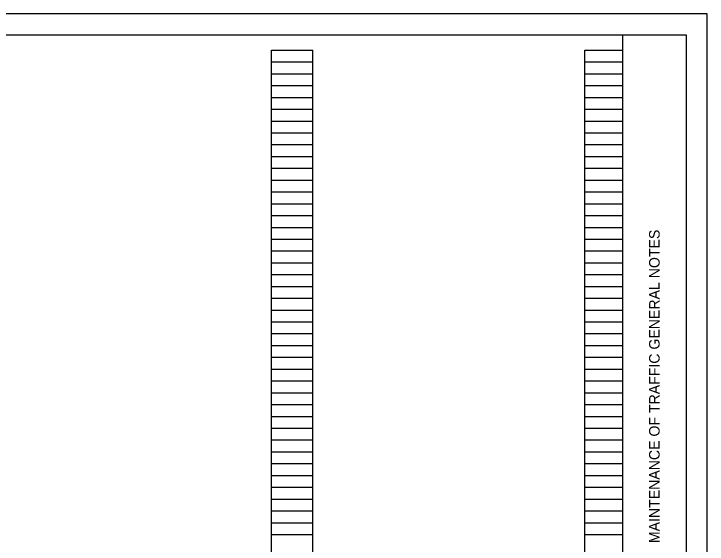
# Model space of a CAD drawing. Extents: x 0 to 34, y 0 to 22.
# Drawn here: x 17.58 to 34, y 9.43 to 22 of the extents above; entities that cross this region are included whole.
import ezdxf

# ---------------------------------------------------------------- set-up
doc = ezdxf.new("R2010")
doc.units = 0
for name, color, linetype in [('SH_Border', 7, 'Continuous'), ('SH_Cut_Line', 7, 'Continuous'), ('SH_Data', 7, 'Continuous')]:
    doc.layers.add(name, color=color, linetype=linetype)

msp = doc.modelspace()

# ---------------------------------------------------------------- linework, layer by layer
at = {"layer": 'SH_Border'}
msp.add_line((32, 0.5), (32, 21.5), dxfattribs=at)
msp.add_lwpolyline([(1.5, 21.5), (33.5, 21.5), (33.5, 0.5), (1.5, 0.5)], close=True, dxfattribs=at)
at = {"layer": 'SH_Cut_Line'}
msp.add_lwpolyline([(0, 0), (34, 0), (34, 22), (0, 22)], close=True, dxfattribs=at)
at = {"layer": 'SH_Data'}
for p, q in [((23.68, 0.98), (23.68, 21.14)), ((23.68, 21.14), (24.66, 21.14)), ((24.66, 0.98), (24.66, 21.14)), ((31.1, 0.98), (31.1, 21.14)), ((31.1, 21.14), (32, 21.14)), ((32, 0.98), (32, 21.14)), ((23.68, 20.86), (24.66, 20.86)), ((31.1, 20.86), (32, 20.86)), ((23.68, 20.58), (24.66, 20.58)), ((31.1, 20.58), (32, 20.58)), ((23.68, 20.3), (24.66, 20.3)), ((31.1, 20.3), (32, 20.3)), ((23.68, 20.02), (24.66, 20.02)), ((31.1, 20.02), (32, 20.02)), ((23.68, 19.74), (24.66, 19.74)), ((31.1, 19.74), (32, 19.74)), ((23.68, 19.46), (24.66, 19.46)), ((31.1, 19.46), (32, 19.46)), ((23.68, 19.18), (24.66, 19.18)), ((31.1, 19.18), (32, 19.18)), ((23.68, 18.9), (24.66, 18.9)), ((31.1, 18.9), (32, 18.9)), ((23.68, 18.62), (24.66, 18.62)), ((31.1, 18.62), (32, 18.62)), ((23.68, 18.34), (24.66, 18.34)), ((31.1, 18.34), (32, 18.34)), ((23.68, 18.06), (24.66, 18.06)), ((31.1, 18.06), (32, 18.06)), ((23.68, 17.78), (24.66, 17.78)), ((31.1, 17.78), (32, 17.78)), ((23.68, 17.5), (24.66, 17.5)), ((31.1, 17.5), (32, 17.5)), ((23.68, 17.22), (24.66, 17.22)), ((31.1, 17.22), (32, 17.22)), ((23.68, 16.94), (24.66, 16.94)), ((31.1, 16.94), (32, 16.94)), ((23.68, 16.66), (24.66, 16.66)), ((31.1, 16.66), (32, 16.66)), ((23.68, 16.38), (24.66, 16.38)), ((31.1, 16.38), (32, 16.38)), ((23.68, 16.1), (24.66, 16.1)), ((31.1, 16.1), (32, 16.1)), ((23.68, 15.82), (24.66, 15.82)), ((31.1, 15.82), (32, 15.82)), ((23.68, 15.54), (24.66, 15.54)), ((31.1, 15.54), (32, 15.54)), ((23.68, 15.26), (24.66, 15.26)), ((31.1, 15.26), (32, 15.26)), ((23.68, 14.98), (24.66, 14.98)), ((31.1, 14.98), (32, 14.98)), ((23.68, 14.7), (24.66, 14.7)), ((31.1, 14.7), (32, 14.7)), ((23.68, 14.42), (24.66, 14.42)), ((31.1, 14.42), (32, 14.42)), ((23.68, 14.14), (24.66, 14.14)), ((31.1, 14.14), (32, 14.14)), ((23.68, 13.86), (24.66, 13.86)), ((31.1, 13.86), (32, 13.86)), ((23.68, 13.58), (24.66, 13.58)), ((31.1, 13.58), (32, 13.58)), ((23.68, 13.3), (24.66, 13.3)), ((31.1, 13.3), (32, 13.3)), ((23.68, 13.02), (24.66, 13.02)), ((31.1, 13.02), (32, 13.02)), ((23.68, 12.74), (24.66, 12.74)), ((31.1, 12.74), (32, 12.74)), ((23.68, 12.46), (24.66, 12.46)), ((31.1, 12.46), (32, 12.46)), ((23.68, 12.18), (24.66, 12.18)), ((31.1, 12.18), (32, 12.18)), ((23.68, 11.9), (24.66, 11.9)), ((31.1, 11.9), (32, 11.9)), ((23.68, 11.62), (24.66, 11.62)), ((31.1, 11.62), (32, 11.62)), ((23.68, 11.34), (24.66, 11.34)), ((31.1, 11.34), (32, 11.34)), ((23.68, 11.06), (24.66, 11.06)), ((31.1, 11.06), (32, 11.06)), ((23.68, 10.78), (24.66, 10.78)), ((31.1, 10.78), (32, 10.78)), ((23.68, 10.5), (24.66, 10.5)), ((31.1, 10.5), (32, 10.5)), ((23.68, 10.22), (24.66, 10.22)), ((31.1, 10.22), (32, 10.22)), ((23.68, 9.94), (24.66, 9.94)), ((31.1, 9.94), (32, 9.94)), ((23.68, 9.66), (24.66, 9.66)), ((31.1, 9.66), (32, 9.66))]:
    msp.add_line(p, q, dxfattribs=at)

# ---------------------------------------------------------------- texts
msp.add_text('MAINTENANCE OF TRAFFIC GENERAL NOTES', height=0.25, rotation=90, dxfattribs=at).set_placement((32.875, 9.455))

doc.saveas('drawing.dxf')
